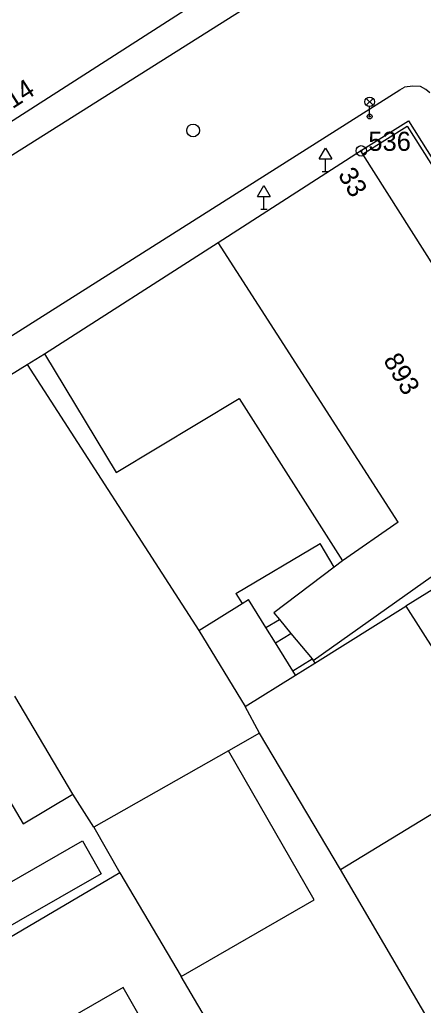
# Model space of a CAD drawing. Extents: x -493753 to -49290, y -1127285 to -112654.
# Drawn here: x -492877.4 to -492845.7, y -1126869.8 to -1126792.4 of the extents above; entities that cross this region are included whole.
import ezdxf

# ---------------------------------------------------------------- set-up
doc = ezdxf.new("R2010")
doc.units = 0
for name, color, linetype in [('Vrstva 10', 7, 'Continuous'), ('Vrstva 11', 7, 'Continuous'), ('Vrstva 27', 7, 'Continuous'), ('Vrstva 33', 7, 'Continuous'), ('Vrstva 34', 7, 'Continuous'), ('Vrstva 43', 7, 'Continuous'), ('Vrstva 44', 7, 'Continuous'), ('Vrstva 5', 7, 'Continuous'), ('Vrstva 63', 7, 'Continuous'), ('Vrstva 7', 7, 'Continuous'), ('Vrstva 8', 7, 'Continuous')]:
    doc.layers.add(name, color=color, linetype=linetype)

msp = doc.modelspace()

# ---------------------------------------------------------------- linework, layer by layer
at = {"layer": 'Vrstva 10'}
msp.add_line((-492847.54, -1126797.89), (-492847.17, -1126797.68), dxfattribs=at)
for points in [[(-492854.19, -1126787.98), (-492891.13, -1126811.28), (-492948.31, -1126847.31), (-492955.31, -1126851.81)], [(-492904.053, -1126954.885), (-492911.56, -1126943.66), (-492926.77, -1126920.75), (-492945.39, -1126892.71), (-492949.82, -1126885.95), (-492959.97, -1126870.68), (-492960.01, -1126868.9), (-492945.16, -1126859.53), (-492913.38, -1126839.48), (-492891.47, -1126825.69), (-492847.54, -1126797.89)], [(-492845.92, -1126797.62), (-492846.52, -1126797.6), (-492847.17, -1126797.68)], [(-492845.18, -1126798.11), (-492845.49, -1126797.86), (-492845.92, -1126797.62)], [(-492875.48, -1126818.62), (-492861.81, -1126809.87)], [(-492875.48, -1126818.62), (-492869.84, -1126827.96), (-492860.17, -1126822.13), (-492852.04, -1126834.91)]]:
    msp.add_lwpolyline(points, dxfattribs=at)
at = {"layer": 'Vrstva 11'}
for points in [[(-492876.84, -1126819.46), (-492863.35, -1126840.38)], [(-492860.43, -1126837.47), (-492853.8, -1126833.54)], [(-492852.69, -1126835.4), (-492853.8, -1126833.54)], [(-492843.76, -1126836.41), (-492847.07, -1126838.47)], [(-492860.43, -1126837.47), (-492859.94, -1126838.25)], [(-492863.35, -1126840.38), (-492859.94, -1126838.25)], [(-492859.94, -1126838.25), (-492859.43, -1126837.94)], [(-492858.07, -1126840.13), (-492859.43, -1126837.94)], [(-492854.21, -1126842.93), (-492847.07, -1126838.47)], [(-492847.07, -1126838.47), (-492839, -1126851.12)], [(-492858.07, -1126840.13), (-492857, -1126839.52)], [(-492857.31, -1126841.35), (-492858.07, -1126840.13)], [(-492863.35, -1126840.38), (-492859.69, -1126846.34)], [(-492857.31, -1126841.35), (-492856.1, -1126840.6)], [(-492855.94, -1126843.54), (-492857.31, -1126841.35)], [(-492855.94, -1126843.54), (-492854.44, -1126842.61)], [(-492855.73, -1126843.88), (-492854.21, -1126842.93)], [(-492854.34, -1126842.73), (-492854.21, -1126842.93)], [(-492859.69, -1126846.34), (-492855.73, -1126843.88)], [(-492855.73, -1126843.88), (-492855.94, -1126843.54)], [(-492873.24, -1126853.23), (-492877.8, -1126845.53)], [(-492858.58, -1126848.45), (-492859.69, -1126846.34)], [(-492881.73, -1126847.86), (-492877.17, -1126855.56)], [(-492858.58, -1126848.45), (-492861.01, -1126849.82)], [(-492852.19, -1126859.15), (-492858.58, -1126848.45)], [(-492861.01, -1126849.82), (-492871.61, -1126855.82)], [(-492854.27, -1126861.54), (-492861.01, -1126849.82)], [(-492852.19, -1126859.15), (-492839, -1126851.12)], [(-492877.17, -1126855.56), (-492873.24, -1126853.23)], [(-492871.61, -1126855.82), (-492873.24, -1126853.23)], [(-492871.61, -1126855.82), (-492869.55, -1126859.41)], [(-492882.27, -1126862.51), (-492872.5, -1126856.91)], [(-492872.5, -1126856.91), (-492871.02, -1126859.49)], [(-492869.55, -1126859.41), (-492887.25, -1126869.81), (-492887.47, -1126869.43)], [(-492871.02, -1126859.49), (-492880.8, -1126865.08)], [(-492869.55, -1126859.41), (-492864.74, -1126867.57)], [(-492844.14, -1126872.92), (-492852.19, -1126859.15)], [(-492864.74, -1126867.57), (-492854.27, -1126861.54)], [(-492856.37, -1126881.76), (-492864.74, -1126867.57)]]:
    msp.add_lwpolyline(points, dxfattribs=at)
at = {"layer": 'Vrstva 27'}
msp.add_circle((-492863.79, -1126801.08), 0.5, dxfattribs=at)
at = {"layer": 'Vrstva 33'}
for p, q in [((-492850.175, -1126798.565), (-492849.645, -1126799.095)), ((-492850.175, -1126799.095), (-492849.645, -1126798.565)), ((-492849.91, -1126799.98), (-492849.91, -1126799.205))]:
    msp.add_line(p, q, dxfattribs=at)
for centre, radius in [((-492849.91, -1126798.83), 0.375), ((-492849.91, -1126799.98), 0.19), ((-492849.91, -1126799.98), 0.05)]:
    msp.add_circle(centre, radius, dxfattribs=at)
at = {"layer": 'Vrstva 34'}
for p, q in [((-492853.89, -1126803.31), (-492853.39, -1126802.46)), ((-492853.39, -1126802.46), (-492852.89, -1126803.31)), ((-492853.89, -1126803.31), (-492852.89, -1126803.31)), ((-492853.39, -1126804.31), (-492853.39, -1126803.31)), ((-492853.64, -1126804.31), (-492853.14, -1126804.31)), ((-492858.72, -1126806.26), (-492858.22, -1126805.41)), ((-492858.22, -1126805.41), (-492857.72, -1126806.26)), ((-492858.72, -1126806.26), (-492857.72, -1126806.26)), ((-492858.22, -1126807.26), (-492858.22, -1126806.26)), ((-492858.47, -1126807.26), (-492857.97, -1126807.26))]:
    msp.add_line(p, q, dxfattribs=at)
at = {"layer": 'Vrstva 5'}
for points in [[(-492878.98, -1126800.93), (-492858.93, -1126788.06), (-492860.11, -1126785.98), (-492861.62, -1126783.3), (-492866.02, -1126775.51)], [(-492861.81, -1126809.87), (-492850.64, -1126802.69), (-492850.48, -1126802.94), (-492840.05, -1126819.37), (-492833.69, -1126829.32)], [(-492847.66, -1126831.87), (-492861.81, -1126809.87)], [(-492847.66, -1126831.87), (-492852.04, -1126834.91)], [(-492852.69, -1126835.4), (-492857.45, -1126838.98), (-492857, -1126839.52)], [(-492852.04, -1126834.91), (-492852.69, -1126835.4)], [(-492854.34, -1126842.73), (-492844.25, -1126835.58)], [(-492857, -1126839.52), (-492856.1, -1126840.6)], [(-492856.1, -1126840.6), (-492854.44, -1126842.61)], [(-492854.44, -1126842.61), (-492854.34, -1126842.73)], [(-492872.01, -1126884.9), (-492862.84, -1126879.71), (-492869.3, -1126868.44), (-492878.43, -1126873.69)]]:
    msp.add_lwpolyline(points, dxfattribs=at)
at = {"layer": 'Vrstva 63'}
for radius in [0.412, 0.05]:
    msp.add_circle((-492850.57, -1126802.68), radius, dxfattribs=at)
at = {"layer": 'Vrstva 7'}
for p, q in [((-492850.64, -1126802.69), (-492846.86, -1126800.33)), ((-492846.86, -1126800.33), (-492841.95, -1126808.12)), ((-492850.48, -1126802.94), (-492846.95, -1126800.74)), ((-492846.95, -1126800.74), (-492842.2, -1126808.28))]:
    msp.add_line(p, q, dxfattribs=at)
at = {"layer": 'Vrstva 8'}
msp.add_lwpolyline([(-492882.12, -1126822.71), (-492876.84, -1126819.46), (-492875.48, -1126818.62)], dxfattribs=at)

# ---------------------------------------------------------------- texts
at = {"layer": 'Vrstva 43'}
msp.add_text('893', height=1.5, rotation=300.67626, dxfattribs=at).set_placement((-492848.878, -1126819.132))
at = {"layer": 'Vrstva 44'}
for s, rotation, p in [('14', 32.69159, (-492877.995, -1126799.411)), ('33', 300.63165, (-492852.443, -1126804.545))]:
    msp.add_text(s, height=1.5, rotation=rotation, dxfattribs=at).set_placement(p)
at = {"layer": 'Vrstva 63'}
msp.add_text(' 536', height=1.5, dxfattribs=at).set_placement((-492850.57, -1126802.68))

doc.saveas('drawing.dxf')
